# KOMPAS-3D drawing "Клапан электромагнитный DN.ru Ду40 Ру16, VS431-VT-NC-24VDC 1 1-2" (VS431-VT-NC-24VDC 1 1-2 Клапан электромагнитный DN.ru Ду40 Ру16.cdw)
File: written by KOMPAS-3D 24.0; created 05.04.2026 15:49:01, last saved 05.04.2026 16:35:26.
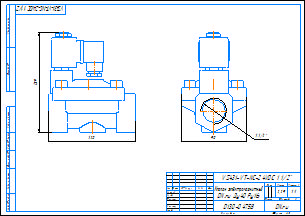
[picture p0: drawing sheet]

Document properties: c3d_UniqueCompID: ef56311e-7521-43dc-8291-0e6108b3d81d; Автор: artio; Класс точности: c; Знак неуказанной шероховатости: Шероховатость не задана; Рассекать на разрезах: Да; c3d_UniqueCompID: ef56311e-7521-43dc-8291-0e6108b3d81d; Автор: artio; Класс точности: c; Знак неуказанной шероховатости: Шероховатость не задана; Рассекать на разрезах: Да; c3d_UniqueCompID: ef56311e-7521-43dc-8291-0e6108b3d81d; Автор: artio; Класс точности: c; Знак неуказанной шероховатости: Шероховатость не задана; Рассекать на разрезах: Да; c3d_UniqueCompID: ef56311e-7521-43dc-8291-0e6108b3d81d; Автор: artio; Класс точности: c; Знак неуказанной шероховатости: Шероховатость не задана; Рассекать на разрезах: Да; Автор: artio; Форматы листов документа: A3; Полное имя файла: VS431-VT-NC-24VDC 1 1-2 Клапан электромагнитный DN.ru Ду40 Ру16.m3d; Масса: 2.285; Наименование: Клапан электромагнитный DN.ru Ду40 Ру16; Количество листов документа: 1; Примечание: D130-04758

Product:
- Body: Тело 1  | qty 1
    Масса: 3.859459
- Part/product: Клапан электромагнитный DN.ru Ду40 Ру16  | designation VS431-VT-NC-24VDC 1 1-2
    Масса: 2.285
    Раздел спецификации: Прочие изделия
    Примечание: D130-04758
    additional columns: ef56311e-7521-43dc-8291-0e6108b3d81d; artio; c; Шероховатость не задана; Да

Views: Вид 1, Спереди
Referenced files in C:\Users\artio\OneDrive\Рабочий стол\Клапан электромагнитный DN.ru\VS431\VS431-ET-NC\: VS431-ET-NC-24VDC 3-4 Клапан электромагнитный DN.ru Ду20 Ру16.m3d, VS431-ET-NC-24VDC 3-4 Клапан электромагнитный DN.ru Ду20 Ру16.cdw
Referenced files in C:\Users\artio\OneDrive\Рабочий стол\Клапан электромагнитный DN.ru\VS431\VS431-VT-NC\: VS431-VT-NC-24VDC 1 1-2 Клапан электромагнитный DN.ru Ду40 Ру16.m3d
Referenced files in C:\Users\artio\OneDrive\Рабочий стол\Клапан электромагнитный DN.ru\VS431\VS431-VT-NC\VS431-VT-NC-24VDC\Ду40\: VS431-VT-NC-24VDC 1 1-2 Клапан электромагнитный DN.ru Ду40 Ру16.m3d
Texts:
  VS431-VT-NC-24VDC 1 1-2
  Клапан электромагнитный
  DN.ru Ду40 Ру16
  VS431-VT-NC-24VDC 1 1/2"
  VS431-VT-NC-24VDC 1 1/2"-
  Клапан электромагнитный DN.ru Ду40 Ру16
  VS431-VT-NC-24VDC 1 1-2 Клапан электромагнитный DN.ru Ду40 Ру16
Dimensions and other numbers on the sheet: 0; 3; 2; 4; 90; 1 1/2"; 1:1; 1; 2,29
